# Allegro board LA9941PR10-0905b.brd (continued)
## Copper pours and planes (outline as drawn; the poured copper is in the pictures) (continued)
+VSBP_AMP_PVCC on TOP (solid shape): 7.09,21.73 7.21,21.6 12.49,21.6 12.61,21.73 12.61,22.3 12.74,22.43 14.45,22.43 14.64,22.24 14.64,21.48 14.14,20.97 14.14,20.14 14.01,20.02 6.83,20.02 4.8,22.05 4.8,22.94 4.99,23.13 5.69,23.13
+VSBP_AMP_PVCC on BOTTOM (solid shape): 6.41,23.57 6.41,22.04 6.28,21.92 4.81,21.92 4.67,22.05 3.09,22.05 3.02,22.11 3.02,22.68 3.21,22.87 4.45,22.87 5.21,23.63 6.35,23.63
+VSBP_AMP_PVCC on BOTTOM (solid shape): outline of 516 points within 13.27,21.37 22.79,33.26
+VSBP_AMP_PVCC on IN3 (solid shape): 6.6,22.74 14.37,22.74 14.67,22.44 14.67,21.53 14.52,21.37 12.41,21.37 12.09,21.69 5.18,21.69 4.69,22.19 4.69,22.97 4.84,23.13 6.21,23.13
ADPIN on TOP (solid shape): 26.6,96.4 26.6,96.25 26.42,96.07 26.42,95.86 26.29,95.72 26.11,95.72 26.11,95.69 25.97,95.69 25.61,95.33 25.61,93.28 24.78,92.44 22.64,92.44 21.8,93.28 21.8,96.12 21.96,96.27 24.61,96.27 24.61,96.15 24.97,95.79 25.32,96.15 25.32,96.27 25.54,96.27 25.87,96.6 26.4,96.6
ADPIN on BOTTOM (solid shape): 26.37,95.51 26.37,88.55 25.54,87.72 25.54,84.72 25.45,84.63 24.28,84.63 23.79,85.12 23.79,85.4 23.39,85.8 22.26,85.8 22.14,85.93 22.14,95.27 22.49,95.63 26.25,95.63
B+ on TOP (solid shape): 44.74,27.7 44.74,26.81 44.49,26.56 44.49,26.17 44.28,25.97 40.75,25.97 40.68,25.89 40.68,25.54 40.55,25.41 39.54,25.41 39.28,25.67 39.28,27.7 39.54,27.95 44.49,27.95
B+ on TOP (solid shape): 236.18,62.04 236.96,62.04 236.96,62.05 237.45,62.05 237.45,62.04 238.16,62.04 238.16,62.05 238.65,62.05 238.65,62.04 239.43,62.04 239.43,62.05 239.96,62.05 241.81,60.21 241.81,52.9 243.58,51.13 243.58,46.11 243.28,45.81 239.57,45.81 234.72,50.66 234.72,61.88 234.88,62.05 236.18,62.05
B+ on TOP (solid shape): outline of 5592 points within 81.27,11.13 134.1,69.63
B+ on BOTTOM (solid shape): 118.02,113.3 118.02,110.88 112.81,110.88 112.56,111.14 112.56,113.55 113.07,114.06 117.26,114.06
B+ on BOTTOM (solid shape): 244.09,47.32 244.09,46.34 243.64,45.89 238.15,45.89 237.55,46.49 237.55,49.47 238.19,50.11 241.3,50.11
B+ on BOTTOM (solid shape): 184.47,128.01 184.47,125.13 184.26,124.92 183.4,124.92 183.25,125.08 183.25,128.07 183.45,128.28 184.2,128.28
B+ on BOTTOM (solid shape): 90.95,26.5 90.95,11.91 90.03,10.99 82.93,10.99 82.61,11.31 82.61,20.45 85.13,22.97 85.13,26.02 85.86,26.75 90.69,26.75
B+ on BOTTOM (solid shape): 151.45,127.75 151.45,124.37 151.19,124.12 149.77,124.12 148.73,125.16 146.72,125.16 146.32,125.56 146.32,127.62 146.72,128.03 151.17,128.03
B+ on BOTTOM (solid shape): 114.24,69.92 115.01,69.92 115.01,69.92 115.51,69.92 115.51,69.92 116.21,69.92 116.21,69.92 116.71,69.92 116.71,69.92 117.49,69.92 117.49,69.92 119.89,69.92 120.16,69.65 120.16,68.65 119.27,67.76 119.27,64.8 118.36,63.89 112.72,63.89 112.22,64.39 112.22,69.44 112.69,69.92 114.24,69.92
B+ on IN1 (solid shape): 132.12,22.31 132.12,21.81 131.99,21.68 130.33,21.68 130.26,21.75 130.26,22.33 130.34,22.42 132.02,22.42
B+ on IN3 (solid shape): outline of 897 points within 100.4,48.01 123.25,69.88
B+ on IN3 (solid shape): outline of 3123 points within 39.18,11.23 89.91,27.95
B+ on VCC: 110.09,67.86 110.45,70.62 110.57,73.4 110.57,104.13 112.07,104.13 112.07,115.13 114.28,115.13 118.05,118.9 114.28,122.67 110.57,122.67 110.57,126.48 110.8,126.48 112.05,127 112.57,128.25 112.57,128.48 117.03,128.48 118.14,125.83 120.8,124.73 123.8,124.73 126.46,125.83 127.57,128.48 191.07,128.48 191.07,125.03 190.58,124.54 183.07,124.54 179.33,120.81 160.64,120.81 156.42,116.59 140.26,116.59 137.32,113.65 136.15,113.65 131.79,109.29 131.79,106.87 125.49,100.52 125.41,100.34 125.41,68.29 124.98,67.86
B++ on TOP (solid shape): 50,26.93 50,22.74 49.57,22.31 45.45,22.31 44.74,21.6 41.57,21.6 41.44,21.48 41.44,21.47 41.25,21.28 41.25,20.65 41.06,20.46 38.65,20.46 38.57,20.54 38.57,24.32 39.41,25.16 43.98,25.16 44.87,26.05 44.87,26.43 45.06,26.62 45.06,27.04 45.22,27.21 49.72,27.21
B++ on BOTTOM (solid shape): 46.04,23.15 46.04,22.54 45.81,22.31 41.49,22.31 40.81,23 40.81,24.31 41.09,24.59 44.6,24.59
BATT+ on BOTTOM (solid shape): 102.3,32.84 102.3,30.55 102.04,30.3 101.28,30.3 101.15,30.17 101.15,28.36 101,28.21 100.75,28.21 100.45,27.9 100.45,24.09 100.37,24.02 97.32,24.02 96.58,24.75 96.58,29.66 96.96,30.04 98.74,30.04 99.12,30.42 99.12,32.58 99.63,33.09 102.04,33.09
BATT++ on TOP (solid shape): 109.69,16.9 109.69,14.71 109.54,14.56 107.81,14.56 107.03,15.34 107.03,15.54 106.72,15.86 106.72,16.92 106.92,17.13 109.46,17.13
BATT++ on BOTTOM (solid shape): 108.47,26.79 108.47,24.94 109.18,24.23 110.13,24.23 110.25,24.12 110.25,17.77 108.81,16.33 103.67,16.33 103.42,16.59 103.42,24.2 102.78,24.84 101.15,24.84 100.9,25.09 100.9,27.76 101.03,27.88 107.38,27.88
BATT_PRS on TOP (solid shape): 99.21,23.36 99.21,20.7 98.61,20.09 96.19,20.09 95.92,20.36 95.92,21.77 97.59,23.44 99.13,23.44
BOOT2 on BOTTOM (solid shape): 123.02,115.68 123.02,115.55 122.97,115.5 120.94,115.5 120.66,115.22 120.66,114.28 120.53,114.16 119.54,114.16 119.44,114.26 119.44,115.2 119.75,115.5 119.78,115.5 120.01,115.73 122.97,115.73
BST1_3V on TOP (solid shape): 43.8,32.58 43.8,30.44 43.7,30.34 42.69,30.34 42.63,30.41 42.63,32.58 42.75,32.71 43.66,32.71
BST1_5V on TOP (solid shape): 54.74,31.74 54.74,29.54 54.63,29.43 54.01,29.43 53.86,29.58 53.86,31.68 53.99,31.81 54.67,31.81
BST_3V on TOP (solid shape): 47.41,32.02 47.41,31.89 47.38,31.86 46.6,31.86 45.2,30.46 44.37,30.46 44.36,30.47 44.36,31.38 44.87,31.38 45.56,32.07 47.36,32.07
BST_5V on TOP (solid shape): 52.41,30.95 52.41,30.9 52.34,30.82 51.83,30.82 50.79,31.86 50.15,31.86 50.13,31.89 50.13,32.07 50.15,32.09 51.27,32.09
BST_+1.5VRUN on TOP (solid shape): 191.07,121.11 191.07,120.59 190.94,120.47 190.12,120.47 190.05,120.53 190.05,121.23 189.67,121.61 189.67,121.93 189.81,122.06 190.11,122.06
BST_+V1.05V on TOP (solid shape): 233.04,66.37 233.04,64.97 232.85,64.78 232.03,64.78 231.9,64.9 231.9,66.3 232.03,66.43 232.98,66.43
BST_+V1.05V on BOTTOM (solid shape): 233.38,66.95 233.38,66.13 233.12,65.86 231.91,65.86 231.76,66.02 231.76,66.25 231.95,66.45 232.35,66.45 232.48,66.58 232.48,66.96 232.54,67.02 233.31,67.02
BTST on BOTTOM (solid shape): 75.73,28.64 75.73,28.44 75.93,28.23 76.87,28.23 77.13,28.49 78.27,28.49 78.35,28.41 78.35,28.28 78.27,28.21 77.36,28.21 76.59,27.44 75.02,27.44 74.89,27.57 74.89,28.54 75.02,28.66 75.71,28.66
CHG_LGATE on BOTTOM (solid shape): 78.67,27.59 78.67,26.66 77.66,25.65 77.66,22.8 77.43,22.57 76.69,22.57 76.56,22.71 76.56,25.3 76.89,25.63 76.89,25.92 78.36,27.39 78.36,27.54 78.47,27.64 78.62,27.64
CHG_LX on BOTTOM (solid shape): 72.17,26.56 72.17,22.75 72.05,22.62 71.29,22.62 71.03,22.87 71.03,26.56 71.16,26.68 72.05,26.68
CHG_LX on BOTTOM (solid shape): 77.24,29.48 78.14,29.48 78.14,29.22 75.98,29.22 75.71,28.96 75.16,28.96 75.09,29.02 75.09,29.92 75.12,29.95 76.77,29.95
CHG_LX on IN1 (solid shape): 72.17,27.19 72.17,26.17 72.05,26.05 71.03,26.05 70.9,26.17 70.9,27.19 71.29,27.57 71.79,27.57
CHG_LX on IN1 (solid shape): 77,29.73 77,29.35 76.87,29.22 74.08,29.22 73.83,29.48 73.83,30.24 76.49,30.24
CHG_UGATE on BOTTOM (solid shape): 77.25,28.97 78.14,28.97 78.14,28.71 77.1,28.71 76.72,28.33 75.98,28.33 75.88,28.44 75.88,28.9 76.07,29.1 77.13,29.1
CHG_UGATE on BOTTOM (solid shape): 71.18,22.39 72.2,22.39 72.3,22.29 72.3,21.48 72.17,21.35 70.73,21.35 70.57,21.5 70.57,22.42 70.7,22.54 71.03,22.54
CHG_UGATE on IN1 (solid shape): 77,28.97 77,28.46 76.62,28.08 75.22,28.08 75.22,29.1 76.87,29.1
CHG_UGATE on IN1 (solid shape): 71.51,23.53 71.51,21.51 71.32,21.32 70.69,21.32 70.49,21.52 70.49,23.62 70.53,23.66 71.38,23.66
CLK_SMB on TOP (solid shape): 102.94,23.1 102.94,20.45 102.7,20.21 102,20.21 101.73,20.48 101.73,23.05 102,23.32 102.72,23.32
DAT_SMB on TOP (solid shape): 100.97,23.03 100.97,20.48 100.65,20.16 99.97,20.16 99.7,20.43 99.7,23.1 99.91,23.31 100.69,23.31
DH_1.35V on TOP (solid shape): 136.1,18.12 136.1,17.58 135.88,17.36 134.48,17.36 134.4,17.43 134.4,18.17 134.53,18.3 135.92,18.3
DH_1.35V on TOP (solid shape): 127.8,16.98 128.66,16.98 128.77,16.88 128.77,16.27 128.66,16.17 127.7,16.17 127.38,16.48 127.38,16.64 127.1,16.93 126.16,16.93 126.11,16.99 126.11,17.09 126.16,17.14 127.64,17.14
DH_1.35V on GND1 (solid shape): 136.31,18.47 136.31,17.76 136.16,17.61 135.04,17.61 134.96,17.69 134.96,18.52 135.06,18.63 136.16,18.63
DH_1.35V on IN1 (solid shape): 136.25,18.23 136.25,17.65 136.04,17.45 134.79,17.45 134.6,17.63 134.6,17.64 133.59,18.66 133.59,19.46 133.64,19.51 134.96,19.51
DH_1.35V on IN1 (solid shape): 129.81,17.77 129.81,17.16 128.79,16.14 127.72,16.14 127.65,16.21 127.65,16.91 127.72,16.99 128.34,16.99 128.82,17.46 128.82,17.72 128.97,17.87 129.71,17.87
DL_1.35V on TOP (solid shape): 126.11,16.35 126.11,16.18 126.89,15.39 126.89,14.83 126.49,14.43 125.82,14.43 125.69,14.56 125.69,14.84 125.84,15 125.84,16.42 125.88,16.46 126,16.46
DL_1.35V on TOP (solid shape): 132.12,11.82 132.12,11.82 132.25,11.69 132.25,10.93 132.12,10.81 130.93,10.81 130.87,10.87 130.87,11.44 131,11.56 131.22,11.56 131.61,11.95 131.99,11.95
DL_1.35V on IN1 (solid shape): 127.06,15.44 127.06,13.79 126.87,13.6 125.92,13.6 125.69,13.83 125.69,15.5 125.88,15.69 126.81,15.69
DL_1.35V on IN1 (solid shape): 132.27,11.82 132.27,10.93 132.14,10.8 129.67,10.8 129.54,10.93 129.54,11.5 129.86,11.82 130.81,11.82 130.82,11.83 131.42,11.83 131.66,12.07 132.01,12.07
ECAGND on TOP (solid shape): 158.94,21.12 159.54,21.12 159.63,21.03 159.63,19.43 159.6,19.4 158.07,19.4 157.99,19.48 157.99,19.97 157.6,20.36 157.6,21.45 157.64,21.49 158.57,21.49
GPU_PVCC on BOTTOM (solid shape): 146.85,124.7 146.85,122.44 146.72,122.31 145.98,122.31 145.6,122.69 145.22,122.69 145.1,122.56 143.83,122.56 143.72,122.66 143.72,122.77 143.78,122.82 144.74,122.82 144.94,123.02 145.86,123.02 146.21,123.38 146.21,124.67 146.34,124.8 146.75,124.8
LG_3V on TOP (solid shape): 41.47,20.1 41.59,20.1 42.08,19.61 42.08,19.04 41.95,18.91 40.65,18.91 40.6,18.96 40.6,19.95 40.76,20.1 41.47,20.1
LG_3V on TOP (solid shape): 48.04,31.2 48.04,30.04 47.91,29.9 47.02,29.9 46.88,30.04 46.88,30.73 47.38,31.23 48.02,31.23
LG_3V on IN4 (solid shape): 41.85,20.52 41.85,19.67 41.72,19.55 40.68,19.55 40.6,19.62 40.6,20.53 40.76,20.68 41.68,20.68
LG_3V on IN4 (solid shape): 48.07,31.13 48.07,28.42 47.93,28.28 47.19,28.28 47.04,28.43 47.04,31.06 47.21,31.23 47.97,31.23
LG_5V on TOP (solid shape): 46.55,17.39 46.55,16.47 46.42,16.34 44.31,16.34 44.23,16.42 44.23,16.93 44.26,16.95 45.05,16.95 45.28,17.18 45.28,17.46 45.43,17.61 46.32,17.61
LG_5V on TOP (solid shape): 49.84,31.24 49.84,30.73 50.85,29.72 50.85,29.51 50.73,29.39 49.83,29.39 49.52,29.7 49.51,29.8 49.47,29.9 49.47,31.2 49.54,31.28 49.8,31.28
LG_5V on IN4 (solid shape): 48.32,17.23 48.32,16.62 48.05,16.34 45.4,16.34 45.25,16.5 45.25,17.44 45.43,17.61 47.94,17.61
LG_5V on IN4 (solid shape): 50.85,29.83 50.85,28.98 50.53,28.66 49.62,28.66 49.49,28.79 49.49,29.57 49.53,29.73 49.49,29.89 49.49,30.08 49.62,30.2 50.47,30.2
LG_+V1.05V on BOTTOM (solid shape): 233.67,69.6 233.67,69.03 233.4,68.77 232.52,68.77 232.47,68.82 232.47,69.49 232.65,69.67 233.6,69.67
LG_+V1.05V on BOTTOM (solid shape): 245.61,68.59 245.61,68.34 245.5,68.24 244.87,68.24 244.43,68.68 243.74,68.68 243.63,68.8 243.63,69.94 243.8,70.12 244.08,70.12
LG_+V1.05V on IN2 (solid shape): 233.63,71.09 233.63,69.26 233.53,69.16 232.56,69.16 232.43,69.29 232.43,71.09 232.6,71.25 233.46,71.25
LG_+V1.05V on IN2 (solid shape): 244.49,71.31 244.49,68.82 244.21,68.54 243.55,68.54 243.33,68.75 243.33,71.3 243.57,71.54 244.26,71.54
LGATE1 on BOTTOM (solid shape): 112.18,79.77 112.18,78.37 111.93,78.12 111.04,78.12 110.66,78.5 110.66,79.64 110.91,79.9 112.05,79.9
LGATE1 on BOTTOM (solid shape): 124.5,112.1 124.4,112 123.99,112 123.86,112.13 123.86,113.17 124.24,113.55 124.24,114.44 124.37,114.57 124.5,114.57
LGATE1 on IN1 (solid shape): 112.18,79.77 112.18,78.88 111.8,78.5 110.78,78.5 110.66,78.63 110.66,79.64 110.91,79.9 112.05,79.9
LGATE1 on IN1 (solid shape): 124.63,113.07 124.63,112.11 124.61,112.09 124.61,111.62 124.14,111.14 123.89,111.14 123.64,110.89 123.64,109.73 123.35,109.44 122.47,109.44 122.25,109.65 122.25,111.11 123.09,111.95 123.47,111.95 123.79,112.27 123.79,113.04 123.91,113.17 124.52,113.17
LGATE2 on BOTTOM (solid shape): 120.49,102.73 120.49,101.61 120.28,101.41 118.94,101.41 118.63,101.71 118.63,102.76 118.78,102.91 120.31,102.91
LGATE2 on BOTTOM (solid shape): 123.31,114.58 123.31,113.04 122.67,112.41 122.37,112.41 122.24,112.53 122.24,112.94 123.1,113.8 123.1,114.59 123.15,114.64 123.25,114.64
LGATE2 on IN1 (solid shape): 120.71,104.23 120.71,102.2 120.13,101.61 119.72,101.61 119.52,101.82 119.52,104.23 119.62,104.33 120.61,104.33
LGATE2 on IN1 (solid shape): 123.31,113.53 123.31,112.89 122.04,111.62 121.43,111.62 121.25,111.8 121.25,112.18 122.64,113.58 123.25,113.58
LX_3V on TOP (solid shape): 46.67,32.47 47.49,32.47 47.54,32.42 47.54,32.27 45.5,32.27 45,31.76 44.99,31.76 44.94,31.71 44.36,31.71 44.33,31.73 44.33,32.6 44.38,32.65 44.97,32.65 45.3,32.98 46.17,32.98
LX_3V on TOP (solid shape): 38.27,23.25 38.27,21.48 38.13,21.34 37.63,21.34 36.97,20.69 36.97,19.7 37.15,19.52 37.81,19.52 37.86,19.57 40.17,19.57 40.17,17.03 39.92,16.78 36.61,16.78 36.11,17.28 36.11,23 36.49,23.38 38.14,23.38
LX_3V on BOTTOM (solid shape): 40.42,24.22 40.42,17.03 40.17,16.78 36.61,16.78 36.11,17.28 36.11,20.15 37,20.15 37,19.7 37.2,19.49 37.66,19.49 38.29,20.13 38.29,20.51 38.14,20.66 37.5,20.66 37,20.15 36.11,20.15 36.11,24.65 36.53,25.07 39.57,25.07
LX_3V on IN4 (solid shape): 37.43,23.36 37.43,22.36 37.25,22.19 36.28,22.19 36.13,22.34 36.13,23.36 36.28,23.51 37.28,23.51
LX_3V on IN4 (solid shape): 46.49,32.87 46.49,32.26 46.42,32.19 45.24,32.19 45.02,32.42 45.02,32.75 45.21,32.93 46.42,32.93
LX_5V on TOP (solid shape): 52.34,32.6 52.34,32.2 52.6,31.94 53.05,31.94 53.27,31.72 53.27,30.8 53.24,30.76 52.67,30.76 52.62,30.81 52.62,31.1 51.45,32.27 50.1,32.27 50.1,32.47 50.81,32.47 51.19,32.85 52.08,32.85
LX_5V on TOP (solid shape): 53.25,24.96 53.25,19.57 53.12,19.44 53.12,16.9 52.87,16.65 47.59,16.65 47.32,16.92 47.32,21.72 47.59,21.98 50,21.98 50.61,22.59 50.61,25.82 50.73,25.94 52.27,25.94
LX_5V on BOTTOM (solid shape): 52.49,32.07 52.49,31.22 52.32,31.05 51.12,31.05 50.99,31.18 50.99,32.41 51.2,32.61 51.95,32.61
LX_5V on BOTTOM (solid shape): 52.21,27.39 52.21,24.96 53.12,24.04 53.12,16.9 52.87,16.65 47.92,16.65 47.35,17.21 47.35,23.96 47.92,24.52 49.7,24.52 49.82,24.65 49.82,27.39 50.23,27.8 51.8,27.8
P1 on TOP (solid shape): 68.36,25.18 68.36,21.85 69.66,20.56 69.66,16.77 69.4,16.52 68.62,16.52 68.62,16.52 65.97,16.52 65.72,16.77 65.72,18.17 65.97,18.42 69.15,18.42 69.15,19.44 68.64,19.95 65.72,19.95 65.72,24.42 66.84,25.53 68.01,25.53
P1 on BOTTOM (solid shape): 67.98,22.75 68.17,22.56 68.17,21.03 67.98,20.84 67.98,17.41 68.05,17.35 68.57,17.35 68.9,17.03 68.9,16.64 68.77,16.52 66.1,16.52 65.82,16.79 65.82,24.53 65.92,24.71 65.87,24.91 65.87,25.24 66.18,25.55 66.18,25.56 66.54,25.92 67.98,25.92
PCH_SPI_CLK on BOTTOM (solid shape): 242.25,13.34 242.25,12.99 242.1,12.83 240.55,12.83 240.37,13.01 240.37,13.27 240.6,13.5 242.1,13.5
PCH_SPI_CS# on BOTTOM (solid shape): 249.48,15.92 249.48,15.46 249.4,15.38 247.77,15.38 247.63,15.52 247.63,15.88 247.78,16.03 249.38,16.03
PCH_SPI_HOLD# on BOTTOM (solid shape): 242.43,14.64 242.43,14.31 242.23,14.1 240.57,14.1 240.35,14.33 240.35,14.54 240.57,14.77 242.3,14.77
PCH_SPI_SI on BOTTOM (solid shape): 242.28,12.12 242.28,11.72 242.15,11.59 240.24,11.59 240.19,11.64 240.19,12 240.4,12.2 242.2,12.2
PCH_SPI_SO on BOTTOM (solid shape): 249.33,14.56 249.33,14.25 249.19,14.11 247.49,14.11 247.31,14.29 247.31,14.56 247.51,14.76 249.13,14.76
PCH_SPI_WP# on BOTTOM (solid shape): 249.63,13.38 249.63,12.81 249.57,12.76 247.87,12.76 247.71,12.9 247.49,12.93 247.47,12.93 247.38,13.02 247.38,13.16 247.56,13.34 247.61,13.4 247.65,13.46 247.66,13.49 249.52,13.49
PHASE1 on BOTTOM (solid shape): 124.9,114.59 124.9,113.53 125.24,113.2 125.24,110.83 125.16,110.75 124.46,110.75 124.3,110.91 124.3,111.55 124.68,111.92 124.68,113.5 124.7,113.52 124.7,114.59 124.75,114.64 124.85,114.64
PHASE1 on BOTTOM (solid shape): 111.95,73.6 111.95,71.95 112.41,71.49 113.17,71.49 113.37,71.29 113.37,70.52 113.2,70.35 111.9,70.35 110.68,71.56 110.68,73.49 110.86,73.67 111.88,73.67
PHASE1 on IN2 (solid shape): 113.55,71.28 113.55,70.92 113.66,70.81 114.36,70.81 114.43,70.75 114.43,69.86 114.23,69.67 112.62,69.67 112.3,69.98 112.3,71.36 112.41,71.46 113.37,71.46
PHASE1 on IN2 (solid shape): 125.26,113.01 125.26,111.87 125.33,111.79 125.33,111.03 124.83,110.52 124.7,110.52 124.47,110.75 124.47,111.74 124.67,111.95 124.67,113.04 124.83,113.19 125.08,113.19
PHASE2 on BOTTOM (solid shape): 120.87,108.42 120.87,107.53 120.69,107.35 118.84,107.35 118.62,107.58 118.62,108.07 119.04,108.5 120.79,108.5
PHASE2 on BOTTOM (solid shape): 123.02,114.87 123.02,114.79 122.82,114.58 122.82,114.01 121.92,113.11 121.92,110.75 121.73,110.56 121.03,110.56 120.9,110.69 120.9,113.53 121.94,114.57 121.94,114.74 122.13,114.93 122.96,114.93
REGN on BOTTOM (solid shape): 78.35,27.9 78.35,27.8 78.25,27.7 78.12,27.7 76.44,26.02 75.63,26.02 75.22,25.62 75.22,24.24 75.05,24.07 73.9,24.07 73.8,24.17 73.8,25.77 74.08,26.05 74.82,26.05 74.94,26.17 74.94,27.06 75.12,27.24 76.62,27.24 77.36,27.98 78.27,27.98
RING2 on TOP (solid shape): 18.96,43.5 19.06,43.5 19.14,43.48 20.64,41.97 20.64,41.67 20.56,41.59 20.23,41.59 18.78,43.04 17.62,43.04 17.54,43.12 17.54,43.55 17.69,43.7 18.76,43.7
RING2 on BOTTOM (solid shape): outline of 117 points within 13.77,43.04 20.13,47.22
RING2 on IN2 (solid shape): 18.59,43.53 18.59,43.17 18.46,43.04 17.63,43.04 17.23,43.44 16.61,43.44 16.25,43.8 16.25,44.07 16.66,44.48 17.64,44.48
RING2 on IN2 (solid shape): 15.95,46.03 15.95,45.27 15.79,45.11 14.93,45.11 14.62,45.41 14.62,45.77 13.09,47.3 12.5,47.3 12.4,47.4 12.4,48.15 12.55,48.31 13.67,48.31
RING2 on IN4 (solid shape): 15.7,46.22 15.7,45.49 15.23,45.02 15.03,45.02 14.62,45.43 14.62,45.99 13.34,47.28 12.74,47.28 12.63,47.39 12.63,48.25 12.69,48.31 13.61,48.31
RING2 on IN4 (solid shape): 17.26,44.33 17.93,44.33 18.6,43.66 18.6,43.19 18.45,43.04 18.35,43.04 18.3,43.04 17.82,43.04 17.77,43.04 17.72,43.04 17.49,43.04 17.16,43.36 16.76,43.36 16.71,43.39 16.64,43.41 16.44,43.61 16.44,43.84 16.99,44.39 17.21,44.39
SLEEVE on TOP (solid shape): 20.18,41.49 20.61,41.49 20.69,41.41 20.69,41.11 20.61,41.03 19.67,41.03 18.56,42.15 18.55,42.16 18.48,42.29 18.35,42.37 18.33,42.38 18.05,42.38 17.97,42.46 17.67,42.46 17.54,42.58 17.54,42.79 17.67,42.91 18.76,42.91
SLEEVE on IN2 (solid shape): outline of 293 points within 2.71,33.82 19.29,42.91
SNUB_3V on BOTTOM (solid shape): 39.54,27.54 39.55,27.47 39.57,27.41 39.57,27.1 39.57,27.09 39.54,26.96 39.55,26.83 39.56,26.8 39.08,26.33 36.65,26.33 36.5,26.48 36.5,27.58 36.68,27.77 39.31,27.77
SNUB_5V on BOTTOM (solid shape): 49.59,26.55 49.59,24.9 49.46,24.77 47.43,24.77 46.99,25.22 46.99,26.3 47.5,26.8 49.34,26.8
SPK_L+ on BOTTOM (solid shape): 5.12,16.14 5.12,15.07 7.12,13.06 7.61,13.06 9.46,11.21 9.46,7.35 9.23,7.12 8.65,7.12 8.34,7.42 8.34,9 8.65,9.3 8.65,10.5 7.83,11.31 6.16,11.31 5.88,11.59 5.88,12.66 3.62,14.92 3.62,16.19 3.72,16.29 4.96,16.29
SPK_L- on BOTTOM (solid shape): 3.39,18.9 3.39,18.32 3.01,17.94 3.01,13.27 3.11,13.17 3.11,11.74 3.9,10.96 5.27,10.96 7.55,8.67 7.55,7.35 7.3,7.09 6.67,7.09 6.39,7.37 6.39,8.24 4.81,9.81 3.11,9.81 1.97,10.96 1.97,18.82 2.1,18.95 3.34,18.95
SPK_LC+ on BOTTOM (solid shape): 7.28,30.69 7.28,29.42 7.07,29.22 7.07,27.67 7,27.59 6.84,27.59 6.74,27.69 6.74,29.27 6.63,29.38 6.63,30.68 6.72,30.77 7.2,30.77
SPK_LC- on BOTTOM (solid shape): 8.37,30.69 8.37,30.21 7.73,29.57 7.73,27.67 7.66,27.59 7.45,27.59 7.4,27.64 7.4,30.74 7.48,30.82 8.24,30.82
SPK_OUT_L+ on BOTTOM (solid shape): 7.76,23.5 7.76,21.75 7.45,21.45 7.45,20.86 5.76,19.17 5.76,18.21 5.14,17.58 5.14,17.05 5.09,17 3.62,17 3.62,17.83 3.65,17.86 4.02,17.86 4.57,18.41 4.57,19.45 5.27,20.15 5.68,20.15 5.9,20.38 5.9,20.96 6.3,21.36 6.68,21.36 7.4,22.08 7.4,23.53 7.5,23.63 7.63,23.63
SPK_OUT_L- on BOTTOM (solid shape): 3.61,20.7 3.61,19.69 3.35,19.42 2.27,19.42 2.1,19.59 2.1,20.71 2.36,20.96 3.35,20.96
SPK_OUT_L- on BOTTOM (solid shape): 9.03,23.53 9.03,20.12 8.52,19.62 7.61,19.62 6.56,18.96 6.31,18.96 6.21,19.06 6.21,19.39 7.78,20.96 7.78,21.37 7.91,21.5 8.37,21.5 8.72,21.85 8.72,23.53 8.8,23.6 8.95,23.6
SPK_OUT_L- on IN1 (solid shape): 3.82,20.4 7.33,20.4 7.45,20.28 7.45,19.49 7.43,19.46 6.51,18.93 4.68,18.93 4.25,19.36 3.94,19.36 3.84,19.38 3.73,19.36 2.37,19.36 2.26,19.48 2.26,20.24 2.26,20.24 2.26,20.72 2.38,20.84 3.38,20.84
SPK_OUT_R+ on BOTTOM (solid shape): 12.28,23.5 12.28,21.72 13.09,20.91 13.7,20.91 13.78,20.84 13.78,19.26 13.86,19.18 13.94,19.04 14.08,18.96 14.54,18.5 15.86,18.5 16.01,18.35 16.01,17.78 15.84,17.6 14.19,17.6 12.46,19.34 12.46,20.56 11.95,21.06 11.95,23.5 12.05,23.6 12.18,23.6
SPK_OUT_R- on BOTTOM (solid shape): 10.98,23.53 10.98,21.6 12.23,20.35 12.23,19.01 13.37,17.86 13.37,17.03 13.3,16.95 11.8,16.95 11.7,17.05 11.7,17.79 11.03,18.45 11.03,20.58 10.65,20.96 10.65,23.53 10.73,23.6 10.91,23.6
SPK_R+ on TOP (solid shape): 15.52,15.23 15.52,15 14.8,14.28 14.06,14.28 13.67,13.9 13.06,13.9 12.7,14.26 12.7,14.72 13.33,15.35 15.4,15.35
SPK_R+ on BOTTOM (solid shape): 15.75,17.03 15.75,15.06 15.56,14.87 14.54,14.87 14.46,14.96 14.46,17.01 14.52,17.08 15.71,17.08
SPK_R- on TOP (solid shape): 9.9,12.91 9.9,12.52 9.16,11.78 7.45,11.78 7.3,11.92 7.3,12.88 7.41,12.98 9.83,12.98
SPK_R- on BOTTOM (solid shape): 13.5,16.25 13.5,14.38 10.9,11.79 9.6,11.79 8.73,12.66 8.73,12.87 8.88,13.02 10.27,13.02 11.82,14.57 11.82,16.33 11.9,16.41 13.34,16.41
SPK_RC+ on BOTTOM (solid shape): 13.88,30.67 13.88,29.95 12.91,28.99 12.91,27.69 12.79,27.57 12.71,27.57 12.61,27.67 12.61,29.34 13.12,29.85 13.12,30.67 13.19,30.74 13.8,30.74
SPK_RC- on BOTTOM (solid shape): 12.86,30.67 12.86,29.9 12.28,29.32 12.28,27.67 12.2,27.59 12.05,27.59 11.95,27.69 11.95,29.88 12.18,30.11 12.18,30.64 12.25,30.72 12.81,30.72
SW_1.35V on TOP (solid shape): 127.26,16.55 127.26,16.43 127.67,16.01 128.44,16.01 128.56,15.89 128.56,15.25 128.31,15 127.49,15 126.32,16.18 126.32,16.38 126.11,16.58 126.11,16.7 126.16,16.75 127.07,16.75
SW_1.35V on TOP (solid shape): 137.58,16.52 137.58,11.95 136.94,11.32 132.63,11.32 132.5,11.44 132.5,13.68 131.95,14.23 131.76,14.23 131.63,14.36 131.63,14.61 131.77,14.74 134.28,14.74 134.4,14.87 134.4,17.03 134.5,17.13 136.98,17.13
SW_1.35V on BOTTOM (solid shape): 137.58,19.24 137.58,11.95 136.94,11.32 132.63,11.32 132.25,11.7 132.25,13.86 131.76,14.34 131.76,14.69 132.25,15.18 132.25,15.66 132.4,15.81 134.71,15.81 136.11,17.21 136.11,19.39 136.39,19.67 137.15,19.67
SW_1.35V on IN1 (solid shape): 132.78,14.93 132.78,14.1 132.59,13.91 130.74,13.91 130.62,14.04 130.62,14.93 130.74,15.06 132.65,15.06
SW_1.35V on IN1 (solid shape): 129.5,15.22 129.5,14.75 129.28,14.54 128.84,14.54 128.83,14.54 128.71,14.54 128.33,14.92 127.49,14.92 127.24,15.17 127.24,15.88 127.32,15.96 128.76,15.96
SW_+1.5VRUN on TOP (solid shape): 189.8,121.15 189.8,120.47 189.74,120.4 188.78,120.4 188.59,120.21 188.59,119.51 188.47,119.39 187.45,119.39 187.26,119.58 187.26,120.98 187.5,121.22 187.82,121.22 188.53,121.93 189.02,121.93
SW_+1.5VRUN on BOTTOM (solid shape): 189.37,123.04 189.37,121.42 189.65,121.14 191.89,121.14 192.06,120.96 192.06,119.14 191.93,119.01 186.99,119.01 186.79,119.2 186.79,120.41 187.97,121.59 187.97,123.05 188,123.08 189.33,123.08
SW_+V1.05V on TOP (solid shape): 248.35,65.58 248.35,64.1 248.2,63.94 246.37,63.94 246.19,64.12 246.19,65.65 246.36,65.81 248.12,65.81
SW_+V1.05V on TOP (solid shape): 235.58,68.21 235.58,66.94 235.52,66.87 234.5,66.87 234.44,66.94 234.44,67.57 234.31,67.7 233.61,67.7 233.55,67.76 233.55,68.14 233.81,68.4 235.39,68.4
SW_+V1.05V on BOTTOM (solid shape): 235.04,68.36 235.04,67.8 234.95,67.71 233.42,67.71 233.4,67.74 232.56,67.74 232.47,67.83 232.47,67.98 232.52,68.03 233.54,68.03 233.95,68.44 234.96,68.44
SW_+V1.05V on BOTTOM (solid shape): 248.6,73.37 248.6,69.38 248.98,69 248.98,63.33 248.84,63.19 247.61,63.19 247.41,63.39 247.41,65.21 247.29,65.34 246.65,65.34 246.26,65.73 245.96,65.73 245.89,65.81 245.89,68.92 243.65,71.16 243.65,74.33 244.11,74.79 247.18,74.79
SW_+V1.05V on IN2 (solid shape): 247.97,65.67 247.97,65.03 247.64,64.7 245.68,64.7 245.68,65.72 245.93,65.97 247.66,65.97
SW_+V1.05V on IN2 (solid shape): 235.67,68.37 235.67,66.05 235.52,65.9 234.86,65.9 234.53,66.23 234.53,67.42 234.16,67.79 233.74,67.79 233.64,67.89 233.64,68.57 233.74,68.68 235.37,68.68
U2_BOOT1 on BOTTOM (solid shape): 143.67,120.89 143.67,120.07 144.41,119.34 144.41,117.86 144.36,117.81 143.47,117.81 143.39,117.89 143.39,118.55 143.52,118.68 143.52,119.74 143.39,119.87 143.39,120.91 143.5,121.01 143.55,121.01
U2_BOOT2 on BOTTOM (solid shape): 144.56,126.4 144.56,125.69 143.67,124.8 143.67,123.93 143.6,123.86 143.5,123.86 143.39,123.96 143.39,125.51 143.6,125.71 143.6,126.45 143.62,126.47 144.49,126.47
U2_LGATE1 on TOP (solid shape): 146.09,121.86 146.09,121.55 146.01,121.48 145.5,121.48 145.35,121.32 143.75,121.32 143.6,121.48 143.6,121.83 143.7,121.93 146.01,121.93
U2_LGATE1 on TOP (solid shape): 161.61,128.21 161.61,126.06 161.46,125.91 160.49,125.91 160.29,126.11 160.29,127.53 160.27,127.55 160.27,128.21 160.46,128.4 161.42,128.4
U2_LGATE1 on BOTTOM (solid shape): 161.59,126.84 161.59,125.54 161.35,125.3 160.59,125.3 160.4,125.5 160.4,126.83 160.49,126.92 161.51,126.92
U2_LGATE1 on BOTTOM (solid shape): 146.72,121.9 146.72,121.34 146.67,121.29 145.2,121.29 144.92,121.57 143.75,121.57 143.7,121.62 143.7,121.75 143.78,121.83 144.99,121.83 145.12,121.95 146.67,121.95
U2_LGATE2 on BOTTOM (solid shape): 171.56,121.17 171.56,120.2 171.41,120.05 170.22,120.05 170.09,120.18 170.09,121.04 170.35,121.3 171.43,121.3
U2_LGATE2 on BOTTOM (solid shape): 146.01,124.32 146.01,123.32 145.83,123.15 144.89,123.15 144.79,123.05 143.8,123.05 143.72,123.12 143.72,123.22 143.83,123.32 144.77,123.32 144.97,123.53 144.97,123.78 145.55,124.37 145.96,124.37
U2_LGATE2 on IN1 (solid shape): 146.77,124.29 146.77,123.32 146.65,123.2 145.45,123.2 145.38,123.27 145.38,124.06 145.68,124.37 146.7,124.37
U2_LGATE2 on IN1 (solid shape): 171.54,121.24 171.54,120.2 171.41,120.07 170.09,120.07 169.99,120.18 169.99,121.22 170.17,121.4 171.38,121.4
U2_LGATE3 on TOP (solid shape): 182.16,120.85 182.03,120.72 181.04,120.72 180.91,120.85 180.91,121.29 180.97,121.36 181.58,121.36 181.9,121.68 181.9,122.44 182.16,122.44
U2_LGATE3 on BOTTOM (solid shape): 182.12,121.81 182.12,120.92 181.99,120.79 178.85,120.79 178.73,120.92 178.73,121.81 178.85,121.93 181.99,121.93
U2_PHASE1 on TOP (solid shape): 156.26,126.88 156.26,126.02 156.03,125.79 154.63,125.79 154.46,125.97 154.46,126.98 154.63,127.16 155.98,127.16
U2_PHASE1 on TOP (solid shape): 147.41,120.99 147.41,120.66 146.98,120.23 144.67,120.23 144.54,120.36 144.54,120.82 144.77,121.04 145.56,121.04 145.86,121.34 147.05,121.34
U2_PHASE1 on BOTTOM (solid shape): 145.65,120.56 145.65,117.89 145.55,117.79 144.64,117.79 144.56,117.86 144.56,120.3 143.7,121.17 143.7,121.24 143.8,121.34 144.87,121.34
U2_PHASE1 on BOTTOM (solid shape): 156.27,126.89 156.27,126.25 156.02,126 156.02,125.62 155.77,125.36 155.13,125.36 155,125.49 155,126.76 155.26,127.01 156.15,127.01
U2_PHASE2 on BOTTOM (solid shape): 171.49,127.14 171.49,126.5 171.23,126.25 171.23,125.87 170.98,125.62 170.17,125.62 170.05,125.74 170.05,126.4 170.35,126.69 170.35,127.14 170.47,127.27 171.36,127.27
U2_PHASE2 on BOTTOM (solid shape): 146.04,126.3 146.04,124.7 145.86,124.52 145.43,124.52 144.82,123.91 144.82,123.65 144.71,123.55 143.78,123.55 143.72,123.6 143.72,123.76 144.36,124.39 144.36,125 144.79,125.43 144.79,126.42 144.87,126.5 145.83,126.5
U2_PHASE2 on IN1 (solid shape): 171.49,128.03 171.49,126.93 171.31,126.75 170.45,126.75 170.35,126.86 170.35,127.14 170.22,127.27 170.22,128.41 171.11,128.41
U2_PHASE2 on IN1 (solid shape): 145.32,126.76 145.32,124.59 145.12,124.39 144.64,124.39 144.36,124.67 144.36,126.96 144.44,127.04 145.05,127.04
U2_PHASE3 on TOP (solid shape): 182.88,126.69 182.88,125.45 182.16,124.73 182.16,123.96 181.9,123.96 181.9,126.67 181.99,126.75 182.81,126.75
U2_PHASE3 on BOTTOM (solid shape): 180.38,127.01 180.38,126.25 180.12,126 179.87,126 179.62,126.25 178.85,126.25 178.73,126.38 178.73,127.14 178.85,127.27 180.12,127.27
U2_PHASE3 on IN4 (solid shape): 182.92,127.41 182.92,125.1 182.69,124.87 182.03,124.87 181.9,125 181.9,125.86 181.6,126.17 179.67,126.17 179.59,126.25 179.59,127.49 179.77,127.67 182.66,127.67
U2_UGATE1 on TOP (solid shape): 144.51,118.96 144.51,118.22 144.36,118.07 143.7,118.07 142.91,118.85 142.91,119.64 143.09,119.82 143.65,119.82
U2_UGATE1 on TOP (solid shape): 154.98,125.21 154.98,124.29 154.83,124.14 154.01,124.14 153.84,124.32 153.84,125.34 153.85,125.35 154.84,125.35
U2_UGATE1 on BOTTOM (solid shape): 143.17,120.94 143.17,119.9 143.37,119.69 143.37,118.75 143.29,118.68 142.99,118.68 142.89,118.78 142.89,120.91 142.99,121.01 143.09,121.01
U2_UGATE1 on BOTTOM (solid shape): 155.11,124.98 155.99,124.98 156.25,124.73 156.25,123.96 156.12,123.84 154.72,123.84 154.34,124.22 154.34,125.11 154.47,125.23 154.85,125.23
U2_UGATE2 on BOTTOM (solid shape): 170.1,127.1 170.1,126.72 169.85,126.47 169.85,125.93 169.6,125.68 168.96,125.68 168.81,125.83 168.81,127.15 168.99,127.33 169.88,127.33
U2_UGATE2 on BOTTOM (solid shape): 143.29,126.22 143.29,125 143.17,124.87 143.17,123.96 143.09,123.88 142.96,123.88 142.89,123.96 142.89,125.26 142.81,125.33 142.81,126.17 142.94,126.3 143.22,126.3
U2_UGATE2 on IN4 (solid shape): 144.11,126.83 144.11,125.74 143.5,125.13 142.96,125.13 142.71,125.38 142.71,126.68 143.32,127.29 143.65,127.29
U2_UGATE2 on IN4 (solid shape): 170.09,128.38 170.09,126.63 169.9,126.44 169.08,126.44 168.82,126.7 168.82,128.35 168.93,128.46 170.01,128.46
U2_UGATE3 on TOP (solid shape): 181.65,125.74 181.65,123.96 181.39,123.96 181.39,124.73 180.76,125.36 180.76,125.36 180.76,125.74 180.89,125.87 181.52,125.87
U2_UGATE3 on BOTTOM (solid shape): 181.61,128.15 181.61,124.98 181.48,124.85 180.85,124.85 180.72,124.98 180.72,127.13 180.27,127.58 178.31,127.58 178.18,127.45 178.18,126.63 177.93,126.37 177.67,126.37 177.42,126.63 177.42,128.09 177.8,128.47 181.29,128.47
UG_3V on TOP (solid shape): 38.24,21.09 38.24,20.21 37.71,19.67 37.22,19.67 37.12,19.77 37.12,20.64 37.68,21.19 38.14,21.19
UG_3V on TOP (solid shape): 47.61,31.64 47.61,31.48 47.54,31.41 47.18,31.41 46.61,30.83 46.61,30.27 45.8,29.46 45.51,29.46 45.33,29.64 45.33,30.4 46.6,31.66 47.59,31.66
UG_3V on IN4 (solid shape): 39.31,21.93 39.31,21.27 37.71,19.67 37.17,19.67 37.12,19.72 37.12,20.74 38.37,21.98 39.26,21.98
UG_3V on IN4 (solid shape): 46.83,31.51 46.83,30.7 46.08,29.96 46.08,29.81 45.72,29.45 44.82,29.45 44.74,29.53 44.74,30.19 46.17,31.62 46.72,31.62
UG_5V on TOP (solid shape): 51.83,30.52 51.83,30.1 52.04,29.89 52.04,28.27 51.83,28.06 51.83,26.78 51.63,26.58 50.73,26.58 50.58,26.73 50.58,27.72 50.76,27.91 50.76,28.84 51.02,29.1 51.02,29.77 49.95,30.85 49.95,31.51 50.08,31.64 50.71,31.64
UG_+V1.05V on BOTTOM (solid shape): 248.5,62.9 248.5,62.01 248.31,61.82 247.48,61.82 247.34,61.96 247.34,62.88 247.51,63.05 248.35,63.05
UG_+V1.05V on BOTTOM (solid shape): 234.28,67.44 234.28,66.4 234.22,66.35 233.61,66.35 233.51,66.45 233.51,67.14 233.39,67.27 232.55,67.27 232.47,67.34 232.47,67.44 232.55,67.52 234.2,67.52
UG_+V1.05V on IN2 (solid shape): 234.17,67.39 234.17,64.9 233.92,64.65 233.41,64.65 233.21,64.85 233.21,67.44 233.31,67.55 234.02,67.55
UG_+V1.05V on IN2 (solid shape): 248.58,62.62 248.58,61.71 248.43,61.56 245.13,61.56 245.01,61.69 245.01,62.64 245.27,62.91 248.29,62.91
UGATE1 on BOTTOM (solid shape): 113.37,73.49 113.37,71.87 113.25,71.74 112.59,71.74 112.18,72.15 112.18,73.52 112.31,73.65 113.22,73.65
UGATE1 on BOTTOM (solid shape): 125.31,114.59 125.31,113.65 126.02,112.94 126.02,111.95 126,111.93 125.46,111.93 125.39,112 125.39,113.25 125.08,113.55 125.08,114.59 125.16,114.66 125.23,114.66
UGATE1 on IN2 (solid shape): 113.4,72.93 113.4,72.17 113.24,72.02 110.68,72.02 110.6,72.09 110.6,72.91 110.78,73.08 113.24,73.08
UGATE1 on IN2 (solid shape): 127.54,113.01 127.54,112.05 127.37,111.87 125.59,111.87 125.39,112.07 125.39,112.2 125.39,112.25 125.39,112.82 125.39,112.86 125.39,113.06 125.51,113.19 127.37,113.19
UGATE2 on BOTTOM (solid shape): 123.06,115.26 123.06,115.2 122.96,115.1 122.01,115.1 121.48,114.57 121.48,114.39 121.27,114.19 121.02,114.19 120.87,114.34 120.87,115.18 121.02,115.33 122.99,115.33
UGATE2 on BOTTOM (solid shape): 119.04,109.31 119.04,108.83 118.36,108.15 118.36,107.49 118.3,107.43 117.43,107.43 117.35,107.51 117.35,108.4 118.43,109.49 118.86,109.49
UGATE2 on IN1 (solid shape): 119.27,110.2 119.27,109.03 118.61,108.37 117.97,108.37 117.84,108.5 117.84,109.92 118.28,110.35 119.11,110.35
UGATE2 on IN1 (solid shape): 121.53,115.2 121.53,114.39 121.32,114.19 120.18,114.19 120.03,114.34 120.03,115.15 120.26,115.38 121.35,115.38
N05583 on TOP (solid shape): 64.45,20.82 64.45,19.34 64.43,19.32 61.02,19.32 61.02,18.55 65.34,18.55 65.47,18.42 65.47,16.52 65.34,16.39 60.26,16.39 59.88,16.77 59.88,21.05 60.3,21.48 63.79,21.48
N05583 on BOTTOM (solid shape): 64.5,20.2 65.29,20.2 65.51,19.98 65.51,16.49 65.42,16.39 60.8,16.39 60.59,16.6 60.59,21.04 60.82,21.27 63.43,21.27
N3514453 on TOP (solid shape): 48.87,31.22 48.87,30.31 48.92,30.26 48.92,30 48.79,29.69 48.98,29.41 48.99,29.41 49.02,29.37 49.15,29.37 49.42,29.37 49.47,29.32 49.46,29.32 49.46,28.2 49.34,28.07 48.63,28.07 48.47,28.23 48.47,29.52 48.57,29.62 48.57,30.25 48.67,30.34 48.67,31.21 48.73,31.27 48.82,31.27
N6650847 on TOP (solid shape): 70.27,25.79 70.27,21.48 70.52,21.22 71.16,21.22 71.41,21.48 72.17,21.48 72.3,21.35 72.3,16.65 72.17,16.52 70.29,16.52 69.91,16.9 69.91,20.71 68.64,21.98 68.62,21.98 68.62,25.79 68.75,25.92 70.14,25.92
N6650847 on BOTTOM (solid shape): 70.27,25.67 70.27,21.35 70.65,20.97 72.05,20.97 72.3,20.71 72.3,16.52 69.63,16.52 68.75,17.41 68.75,25.98 68.78,26.02 69.92,26.02
N6654636 on BOTTOM (solid shape): 65.06,30.25 65.06,29.67 65.42,29.32 65.42,28.2 65.85,27.77 67.21,27.77 67.24,27.73 67.24,27.1 67.12,26.97 64.88,26.97 64.31,27.54 64.31,30.22 64.41,30.32 64.98,30.32
N6682601 on BOTTOM (solid shape): 74.51,29.93 74.51,27.34 74.82,27.04 74.82,26.33 74.69,26.2 73.72,26.2 73.65,26.28 73.65,29.91 73.75,30.01 74.44,30.01
N17034092 on TOP (solid shape): 48.47,31.22 48.47,29.67 48.13,29.33 48.13,29.1 48.07,29.04 46.55,29.04 46.55,29.63 46.65,29.73 47.07,29.73 47.08,29.74 47.95,29.74 48.27,30.06 48.27,31.22 48.31,31.27 48.42,31.27
N19849916 on TOP (solid shape): 191.07,119.83 191.07,119.07 191.01,119.01 188.85,119.01 188.78,119.07 188.78,119.77 188.91,119.9 191.01,119.9
N19912586 on TOP (solid shape): 171.05,118.17 171.05,116.38 170.95,116.28 169.21,116.28 169.05,116.44 169.05,118.52 169.16,118.63 170.59,118.63
N19912586 on BOTTOM (solid shape): 169.84,121.2 169.84,116.34 169.33,115.84 165.52,115.84 164.88,116.47 164.88,121.12 165.09,121.32 169.71,121.32
N48711504 on TOP (solid shape): 115.44,84.21 115.44,82.94 115.19,82.68 112.5,82.68 112.28,82.9 112.28,84.16 112.52,84.4 115.25,84.4
N48711504 on BOTTOM (solid shape): 118.53,90.06 118.53,86.25 118.28,85.99 113.18,85.99 113.13,85.94 113.13,85.04 113.19,84.98 118.4,84.98 118.53,84.85 118.53,80.02 117.44,78.93 116.69,78.93 115.89,78.12 112.69,78.12 112.41,78.4 112.41,79.89 112.2,80.09 111.62,80.09 111.57,80.15 110.78,80.15 110.66,80.28 110.66,90.06 111.04,90.44 118.15,90.44
N49558169 on TOP (solid shape): 115.38,81.22 115.38,79.45 115.12,79.19 113.73,79.19 113.47,79.45 113.47,81.35 113.6,81.48 115.12,81.48
N51197016 on BOTTOM (solid shape): 252.62,74.33 252.62,72.13 252.98,71.76 255.46,71.76 256.09,71.13 256.09,69.35 256.47,68.97 257.05,65.98 258,62.68 259.08,60.27 259.08,58.43 258.13,57.48 255.78,57.48 255.52,57.73 255.52,61.39 255.38,61.53 254.97,61.53 253.25,63.24 253.25,64.37 252.89,64.73 249.66,64.73 249.43,64.96 249.43,74.34 249.75,74.66 252.29,74.66
N52999986 on BOTTOM (solid shape): 45.46,48.41 45.46,46.38 45.27,46.19 44.48,46.19 44.32,46.02 44.32,44.18 43.73,43.6 43.73,41.8 42.95,41.02 42.95,40.31 42.95,40.31 42.95,39.45 42.85,39.35 41.49,39.35 41.19,39.65 41.19,42.98 42.35,44.13 42.35,48.25 42.71,48.62 45.23,48.62 45.24,48.63
N85751893 on TOP (solid shape): 248.32,67.6 248.32,66.74 248.15,66.56 246.19,66.56 245.05,67.7 245.05,68.36 245.2,68.52 247.41,68.52
N89512774 on TOP (solid shape): 68,32.24 68,29.75 68.18,29.57 68.53,29.57 68.8,29.29 68.8,28.49 68.58,28.27 68.23,28.27 68.09,28.13 68.09,26.29 67.96,26.16 66.52,26.16 66.33,26.34 66.33,32.14 66.6,32.4 67.84,32.4
N89515927 on BOTTOM (solid shape): 64.2,26.42 64.2,22.36 64.07,22.23 60.8,22.23 60.26,22.77 60.26,26.55 60.62,26.91 63.71,26.91
N89520789 on BOTTOM (solid shape): 118.15,102.88 118.15,97.42 117.51,96.79 113.27,96.79 113.23,96.75 113.23,95.83 113.28,95.77 117.77,95.77 118.15,95.39 118.15,91.45 117.64,90.94 110.91,90.94 110.66,91.2 110.66,100.22 111.04,100.6 112.94,100.6 114.34,101.99 114.34,102.76 114.59,103.01 118.02,103.01
N91124401 on BOTTOM (solid shape): 17.82,111.29 17.82,108.85 18.07,108.6 18.07,107.01 17.76,106.7 16.68,106.7 16.33,107.05 16.33,111.3 16.39,111.37 17.74,111.37
N96795421 on TOP (solid shape): outline of 179 points within 268.59,28.21 274.66,31.94
N96795421 on BOTTOM (solid shape): 269.14,33.01 269.14,32.65 269.05,32.46 269.14,32.26 269.14,32.17 269.36,31.96 269.36,31.95 269.41,31.87 269.49,31.81 269.5,31.81 269.57,31.75 269.57,31.52 269.53,31.48 269.51,31.48 269.34,31.23 269.53,30.99 269.57,30.98 269.57,30.74 269.47,30.65 269.44,30.62 269.42,30.6 269.2,30.6 268.52,31.28 268.52,31.3 268.45,31.41 268.34,31.48 268.32,31.48 268.1,31.71 268.1,32.16 268.22,32.28 268.27,32.44 268.27,32.46 268.89,33.08 269.07,33.08
N97573639 on TOP (solid shape): 260.98,51.19 260.98,50.84 260.46,50.84 260.46,50.4 260.98,50.4 260.98,49.22 260.73,48.97 259.78,48.97 259.52,49.22 259.52,51.06 259.71,51.25 260.92,51.25
N97573639 on BOTTOM (solid shape): 268.54,33.79 268.54,33.35 268.44,33.25 268.34,33.22 268.27,33.3 268.03,33.56 267.69,33.45 267.64,33.1 267.93,32.91 267.95,32.91 268,32.86 267.92,32.78 267.9,32.78 267.75,32.72 267.65,32.6 267.64,32.58 267.27,32.58 267.15,32.7 267.17,32.73 267.21,32.85 267.19,32.96 267.18,32.99 266.95,33.22 266.95,33.24 266.9,33.41 266.76,33.53 266.76,33.79 266.86,33.87 266.95,33.98 268.35,33.98
N98184072 on TOP (solid shape): 255.78,41.28 255.78,39.47 255.36,39.06 251.99,39.06 251.61,39.44 251.61,40.73 251.75,40.87 252.15,40.87 252.15,40.34 252.85,40.34 252.85,40.87 253.35,40.87 253.35,40.34 254.05,40.34 254.05,40.87 254.69,40.87 254.71,40.88 254.72,40.88 254.73,40.9 254.73,41.34 254.79,41.41 255.65,41.41
N98184072 on TOP (solid shape): 261.3,31.12 261.3,30.49 261.49,30.3 262.06,30.3 262.25,30.11 262.25,27.59 261.98,27.32 261.94,27.32 261.94,27.28 261.76,27.1 261.26,27.1 261.2,27.15 261.13,27.15 261.06,27.22 261.06,27.79 261.16,27.88 261.17,27.89 261.41,28.05 261.42,28.34 261.41,28.35 261.41,28.92 261.52,29.44 261,29.41 260.91,29.41 260.84,29.48 260.77,29.52 260.55,29.54 260.38,29.43 260.36,29.41 260.3,29.41 260.28,29.42 260.21,29.48 260.13,29.51 260.12,29.51 259.84,29.79 259.84,30.06 259.85,30.12 259.86,30.17 259.86,30.67 259.84,30.69 259.84,31.12 259.9,31.19 261.24,31.19
N98184072 on IN2 (solid shape): outline of 1556 points within 253.24,27 263.97,42.11
N108767585 on TOP (solid shape): 80.39,20.19 80.39,19.17 80.27,19.05 78.1,19.05 78,19.15 78,20.22 78.08,20.3 80.28,20.3
N108767585 on BOTTOM (solid shape): 82.21,21.3 82.21,11.57 81.95,11.32 78.65,11.32 77.89,12.08 77.89,14.36 76.62,15.63 76.62,21.98 76.75,22.11 81.4,22.11
N110740517 on TOP (solid shape): 79.85,17.47 79.85,16.45 79.57,16.18 76.87,16.18 76.49,16.56 76.49,17.41 76.75,17.67 79.65,17.67
N110805086 on BOTTOM (solid shape): 60.25,35.4 60.25,34.21 60.15,34.1 59.45,34.1 58.97,33.61 58.45,33.61 58.23,33.84 58.23,34.82 58.89,35.48 60.17,35.48
N110833422 on TOP (solid shape): 162.89,118.69 162.89,117.55 162.73,117.39 160.55,117.39 160.27,117.67 160.27,118.72 160.37,118.82 162.76,118.82
N110833422 on BOTTOM (solid shape): 162.43,124.53 162.43,124.21 162.88,123.77 163.87,123.77 164.5,123.13 164.5,116.73 163.49,115.71 159.3,115.71 158.66,116.34 158.66,119.39 160.31,121.04 160.31,124.6 160.57,124.85 162.11,124.85
N110836908 on TOP (solid shape): 175.91,120.14 175.91,118.44 175.82,118.35 174.21,118.35 174.02,118.54 174.02,120.03 174.26,120.27 175.78,120.27
N110836908 on BOTTOM (solid shape): 178.35,121.55 178.35,117.04 177.33,116.03 173.9,116.03 173.27,116.66 173.27,121.87 173.39,122 177.9,122
N110936515 on BOTTOM (solid shape): 145.91,127.85 145.91,127.24 145.84,127.17 143.63,127.17 143.57,127.22 143.57,127.83 143.68,127.93 145.84,127.93
N111178724 on TOP (solid shape): 32.53,93.03 32.53,90.03 33.36,89.19 33.36,88.04 33.29,87.96 28.7,87.96 28.57,88.1 28.57,88.39 28.21,88.75 28.21,92.47 28.84,93.1 32.45,93.1
N111178724 on BOTTOM (solid shape): 33.97,95.26 33.97,88.59 33.34,87.96 28.69,87.96 28.56,88.09 28.56,88.45 28.41,88.6 28.41,95.51 28.5,95.6 33.63,95.6
N111178724 on GND1 (solid shape): 32.1,89.9 32.1,88.1 31.96,87.96 28.62,87.96 28.53,88.05 28.53,88.35 28.36,88.51 28.36,90.33 28.86,90.82 31.19,90.82
N111178724 on GND3 (solid shape): 33.49,90.71 33.49,88.22 33.24,87.97 28.64,87.97 28.51,88.1 28.51,90.46 28.84,90.79 33.41,90.79
N112208327 on BOTTOM (solid shape): 16.87,99.71 16.87,98.06 16.55,97.74 14.52,97.74 14.2,97.42 12.8,97.42 12.61,97.61 12.61,99.64 12.93,99.96 16.61,99.96
N116494866 on TOP (solid shape): 185.93,121.17 185.93,119.58 185.86,119.51 184.72,119.51 184.53,119.71 184.53,119.96 184.34,120.15 183.39,120.15 183.26,120.28 183.26,121.1 183.39,121.23 185.86,121.23
N116495432 on BOTTOM (solid shape): 113.85,102.75 113.85,102.12 113.54,101.8 110.81,101.8 110.68,101.93 110.68,102.88 110.74,102.94 113.66,102.94
N116496514 on TOP (solid shape): 170.92,120.01 170.92,118.99 170.91,118.99 169.27,118.99 169.26,119 169.26,119.89 168.76,120.39 168.76,121.04 168.76,121.05 169.88,121.05

Small or netless copper shapes (teardrops, artwork), in the pictures only: 19 on TOP, 269 on BOTTOM, 2 on GND1, 1 on GND3

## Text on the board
Ref Des/Silkscreen Bottom: HDD | FAN 1 | BATT | eDP | KB | BACKLIGHT | BTB | MSATA | DC | TOUCH | NFC | SUPPORT | DDR3-L | DIMM-A | ONLY | TP | DIMM-B
User.Comments: 2013-09-05 | 2014-09-05 | Fisher | LA-9941P | VAUB0 | 1.0(A00)
BODY_CENTER: 3.7mil | 5.1mil | 4mil | 5.1/3.9 | 4/6 | L2/L4 | L4/L7 | L7/L9 | L9 | Ref | L2
USER_PART_NUM_BOTTOM: FIGURE | SIZE | 8.0 | 10.0 | 20.0 | 26.0 | 30.0 | 36.0 | 83.0 | 91.0 | 98.0 | 130.0 | 146.0 | 154.0 | 35.0 | 39.0 | 40.0 | 43.0 | 63.0 | 236.0 | 33.0x14.0 | 59.0x24.0 | 67.0x16.0 | 67.0x39.0 | 71.0x28.0 | 75.0x24.0 | 75.0x28.0 | 98.0x83.0 | 161.0x146.0 | DRILL CHART: TOP to BOTTOM | ALL UNITS ARE IN MILS | PLATED | NON-PLATED | QTY | 4754 | 1066 | 29 | 2 | 18 | 1 | 3 | 26 | 7 | 4 | 8
DEVICE_TYPE_BOTTOM: FIGURE | SIZE | 8.0 | DRILL CHART: GND1 to GND3 | ALL UNITS ARE IN MILS | PLATED | QTY | 376
COMPVAL_TYPE_BOTTOM: FIGURE | SIZE | 4.0 | DRILL CHART: GND3 to BOTTOM | ALL UNITS ARE IN MILS | PLATED | QTY | 683
COMPVAL_TYPE_TOP: FIGURE | SIZE | 4.0 | DRILL CHART: TOP to GND1 | ALL UNITS ARE IN MILS | PLATED | QTY | 485
PAGE_OUTLINE: FIGURE | SIZE | 4.0 | DRILL CHART: GND1 to IN1 | ALL UNITS ARE IN MILS | PLATED | QTY | 126
User.7: FIGURE | SIZE | 4.0 | DRILL CHART: IN4 to GND3 | ALL UNITS ARE IN MILS | PLATED | QTY | 101
User.35: VIN | +5VALW | +3VS | B+ | +VCC_CORE | GND | +GPU_CORE | +VCCP
